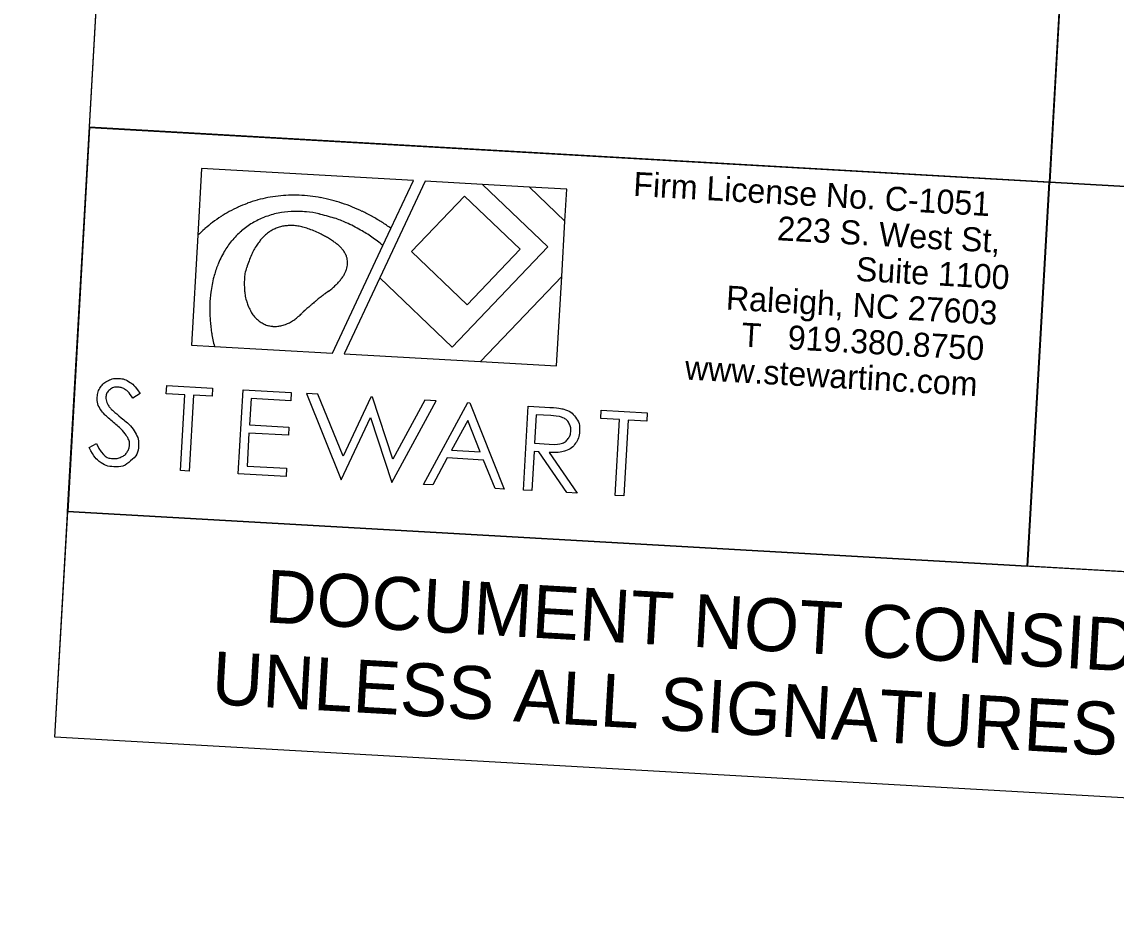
# Model space of a CAD drawing. Extents: x 2604316 to 2606605, y 617090 to 619543.
# Drawn here: x 2605834.5 to 2605948.3, y 618780.5 to 618872.2 of the extents above; entities that cross this region are included whole.
import ezdxf

# ---------------------------------------------------------------- set-up
doc = ezdxf.new("R2010")
doc.units = 0
for name, color, linetype in [('Default', 7, 'Continuous'), ('Scratch_Level_1', 7, 'Continuous'), ('Sheet Plan And Profile CELL', 7, 'Continuous')]:
    doc.layers.add(name, color=color, linetype=linetype)

msp = doc.modelspace()

# ---------------------------------------------------------------- linework, layer by layer
at = {"layer": 'Default'}
for p, q in [((2605947.83, 618967.86), (2605941.44, 618855.58)), ((2605853.21, 618856.96), (2605852.82, 618850.02)), ((2605875.25, 618855.7), (2605853.21, 618856.96)), ((2605876.48, 618855.63), (2605871.75, 618845.57)), ((2605872.91, 618850.72), (2605875.25, 618855.7)), ((2605882.42, 618855.29), (2605876.48, 618855.63)), ((2605882.42, 618855.29), (2605889.22, 618848.8)), ((2605887.31, 618855.02), (2605882.42, 618855.29)), ((2605889.22, 618848.8), (2605882.42, 618855.29)), ((2605891.19, 618854.79), (2605887.31, 618855.02)), ((2605887.31, 618855.02), (2605891, 618851.49)), ((2605891, 618851.49), (2605887.31, 618855.02)), ((2605891, 618851.49), (2605891.19, 618854.79)), ((2605859.05, 618853.68), (2605859, 618853.67)), ((2605865.58, 618853.92), (2605865.59, 618853.92)), ((2605857.96, 618853.34), (2605857.94, 618853.31)), ((2605865.4, 618852.22), (2605865.44, 618852.24)), ((2605870.96, 618851.95), (2605870.97, 618851.95)), ((2605890.67, 618845.73), (2605891, 618851.49)), ((2605872.08, 618848.95), (2605872.91, 618850.72)), ((2605852.82, 618850.02), (2605852.17, 618838.58)), ((2605866.82, 618837.75), (2605872.08, 618848.95)), ((2605889.22, 618848.8), (2605879.27, 618838.39)), ((2605879.27, 618838.39), (2605889.22, 618848.8)), ((2605880.84, 618842.77), (2605886.36, 618848.55)), ((2605890.67, 618845.73), (2605882.21, 618836.87)), ((2605882.21, 618836.87), (2605890.67, 618845.73)), ((2605890.14, 618836.42), (2605890.67, 618845.73)), ((2605871.75, 618845.57), (2605868.05, 618837.68)), ((2605879.27, 618838.39), (2605871.75, 618845.57)), ((2605871.75, 618845.57), (2605879.27, 618838.39)), ((2605852.17, 618838.58), (2605854.54, 618838.45)), ((2605854.54, 618838.45), (2605866.82, 618837.75)), ((2605868.05, 618837.68), (2605882.21, 618836.87)), ((2605882.21, 618836.87), (2605890.14, 618836.42)), ((2605865.31, 618833.5), (2605864.12, 618833.57)), ((2605864.12, 618833.57), (2605867.74, 618824.6)), ((2605867.93, 618827.03), (2605865.31, 618833.5)), ((2605870.81, 618833.19), (2605867.93, 618827.03)), ((2605870.98, 618833.18), (2605870.81, 618833.19)), ((2605873.09, 618826.74), (2605870.98, 618833.18)), ((2605872.99, 618824.3), (2605877.61, 618832.8)), ((2605876.42, 618832.87), (2605873.09, 618826.74)), ((2605877.61, 618832.8), (2605876.42, 618832.87)), ((2605867.74, 618824.6), (2605870.77, 618831.06)), ((2605870.77, 618831.06), (2605872.99, 618824.3)), ((2605837.94, 618797.83), (2605839.28, 618821.29)), ((2605837.94, 618797.83), (2605839.28, 618821.29)), ((2605839.28, 618821.29), (2606038.99, 618809.92)), ((2605839.28, 618821.29), (2606038.99, 618809.92)), ((2606037.66, 618786.46), (2605837.94, 618797.83)), ((2606037.66, 618786.46), (2605837.94, 618797.83))]:
    msp.add_line(p, q, dxfattribs=at)
for points in [[(2605841.54, 618861.23), (2605941.38, 618855.54), (2605939.1, 618815.61), (2605839.27, 618821.29)], [(2605941.38, 618855.54), (2605841.54, 618861.23), (2605839.27, 618821.29), (2605939.1, 618815.61)], [(2605941.43, 618855.54), (2606041.27, 618849.85), (2606038.99, 618809.92), (2605939.15, 618815.61)]]:
    msp.add_lwpolyline(points, close=True, dxfattribs=at)
for points in [[(2605875.04, 618848.31), (2605880.56, 618854.09), (2605886.36, 618848.55), (2605880.84, 618842.77), (2605875.04, 618848.31)], [(2605886.36, 618848.55), (2605880.56, 618854.09), (2605875.04, 618848.31), (2605880.84, 618842.77)], [(2605856.98, 618852.92), (2605857.06, 618852.96)], [(2605867.05, 618851.79), (2605867.01, 618851.78)], [(2605853.57, 618850.7), (2605853.5, 618850.66)], [(2605866.17, 618844.02), (2605866.05, 618843.93)], [(2605866.36, 618844.15), (2605866.28, 618844.1)], [(2605866.5, 618844.23), (2605866.42, 618844.19)], [(2605863.86, 618842.11), (2605863.75, 618842.01)], [(2605849.53, 618833.54), (2605849.58, 618834.39), (2605854.36, 618834.12), (2605854.32, 618833.27), (2605852.37, 618833.38), (2605851.92, 618825.5), (2605851.03, 618825.55), (2605851.48, 618833.43), (2605849.53, 618833.54)], [(2605846.81, 618833.55), (2605846.06, 618833.06)], [(2605857.53, 618833.94), (2605862.53, 618833.66), (2605862.49, 618832.8), (2605858.35, 618833.04), (2605858.19, 618830.3), (2605862.29, 618830.07), (2605862.25, 618829.21), (2605858.14, 618829.44), (2605857.95, 618826.01), (2605862.05, 618825.78), (2605862, 618824.92), (2605857.03, 618825.21), (2605857.53, 618833.94)], [(2605881.11, 618832.6), (2605884.69, 618823.63), (2605883.74, 618823.68), (2605882.53, 618826.64), (2605878.77, 618826.86), (2605877.25, 618824.05), (2605876.28, 618824.11), (2605880.9, 618832.61), (2605881.11, 618832.6)], [(2605889.37, 618827.43), (2605892.28, 618823.2), (2605891.2, 618823.26), (2605888.29, 618827.49), (2605887.8, 618827.52), (2605887.57, 618823.47), (2605886.7, 618823.52), (2605887.19, 618832.25)], [(2605887.19, 618832.25), (2605888.93, 618832.15)], [(2605888.02, 618831.35), (2605887.85, 618828.38), (2605889.35, 618828.28)], [(2605889.55, 618831.26), (2605888.02, 618831.35)], [(2605894.73, 618830.96), (2605894.78, 618831.82), (2605899.56, 618831.55), (2605899.51, 618830.69), (2605897.57, 618830.8), (2605897.12, 618822.92), (2605896.23, 618822.97), (2605896.67, 618830.85), (2605894.73, 618830.96)], [(2605880.89, 618830.76), (2605879.22, 618827.68), (2605882.2, 618827.51), (2605880.89, 618830.76)], [(2605841.51, 618827.94), (2605842.28, 618828.35)]]:
    msp.add_lwpolyline(points, dxfattribs=at)
for centre, radius, start, end in [((2605862.76, 618840.07), 14.11, 105.4351, 109.8733), ((2605862.76, 618840.07), 14.11, 105.4351, 109.8733), ((2605862.65, 618840.64), 13.53, 100.9183, 105.4351), ((2605862.65, 618840.64), 13.53, 100.9183, 105.4351), ((2605862.76, 618840.07), 14.11, 96.4841, 100.9183), ((2605862.76, 618840.07), 14.11, 96.4841, 100.9183), ((2605862.78, 618839.88), 14.3, 92.0792, 96.4841), ((2605862.78, 618839.88), 14.3, 92.0792, 96.4841), ((2605862.79, 618839.62), 14.57, 87.7544, 92.0792), ((2605862.79, 618839.62), 14.57, 87.7544, 92.0792), ((2605862.76, 618838.73), 15.45, 83.5548, 87.7544), ((2605862.76, 618838.73), 15.45, 83.5548, 87.7544), ((2605862.76, 618838.73), 15.45, 79.4225, 83.5548), ((2605862.76, 618838.73), 15.45, 79.4225, 83.5548), ((2605862.48, 618837.28), 16.93, 75.4903, 79.4225), ((2605862.48, 618837.28), 16.93, 75.4903, 79.4225), ((2605862.62, 618837.84), 16.35, 71.6037, 75.4903), ((2605862.62, 618837.84), 16.35, 71.6037, 75.4903), ((2605862.39, 618840.98), 13.11, 118.7212, 123.1234), ((2605862.39, 618840.98), 13.11, 118.7212, 123.1234), ((2605862.95, 618839.96), 14.27, 114.3893, 118.7212), ((2605862.95, 618839.96), 14.27, 114.3893, 118.7212), ((2605862.39, 618840.98), 13.11, 109.8733, 114.3893), ((2605862.39, 618840.98), 13.11, 109.8733, 114.3893), ((2605862.93, 618843.83), 8.65, 92.7105, 101.7301), ((2605862.93, 618843.83), 8.65, 92.7105, 101.7301), ((2605863.08, 618840.53), 11.96, 85.0393, 92.7105), ((2605863.08, 618840.53), 11.96, 85.0393, 92.7105), ((2605861.89, 618835.63), 18.68, 67.9682, 71.6037), ((2605861.89, 618835.63), 18.68, 67.9682, 71.6037), ((2605862.32, 618836.7), 17.52, 64.3511, 67.9682), ((2605862.32, 618836.7), 17.52, 64.3511, 67.9682), ((2605860.99, 618833.93), 20.6, 61.0149, 64.3511), ((2605860.99, 618833.93), 20.6, 61.0149, 64.3511), ((2605862.75, 618840.3), 13.88, 127.2527, 131.4472), ((2605862.75, 618840.3), 13.88, 127.2527, 131.4472), ((2605863.37, 618839.49), 14.9, 123.1234, 127.2527), ((2605863.37, 618839.49), 14.9, 123.1234, 127.2527), ((2605862.63, 618844.36), 8.06, 110.9978, 120.9124), ((2605862.63, 618844.36), 8.06, 110.9978, 120.9124), ((2605863.04, 618843.27), 9.23, 101.7301, 110.9978), ((2605863.04, 618843.27), 9.23, 101.7301, 110.9978), ((2605863.23, 618842.28), 10.21, 77.5039, 85.0393), ((2605863.23, 618842.28), 10.21, 77.5039, 85.0393), ((2605861.98, 618836.81), 15.79, 71.4506, 77.5039), ((2605861.98, 618836.81), 15.79, 71.4506, 77.5039), ((2605863.17, 618840.24), 12.19, 65.3226, 71.4506), ((2605863.17, 618840.24), 12.19, 65.3226, 71.4506), ((2605859.92, 618833.15), 19.99, 60.538, 65.3226), ((2605859.92, 618833.15), 19.99, 60.538, 65.3226), ((2605861.39, 618834.66), 19.77, 57.6686, 61.0149), ((2605861.39, 618834.66), 19.77, 57.6686, 61.0149), ((2605861.39, 618834.66), 19.77, 54.3325, 57.6686), ((2605861.39, 618834.66), 19.77, 54.3325, 57.6686), ((2605862.95, 618839.96), 14.27, 131.4472, 135.2253), ((2605862.95, 618839.96), 14.27, 131.4472, 135.2253), ((2605863.13, 618843.79), 8.82, 130.9224, 140.4448), ((2605863.13, 618843.79), 8.82, 130.9224, 140.4448), ((2605862.59, 618844.43), 7.98, 120.9124, 130.9224), ((2605862.59, 618844.43), 7.98, 120.9124, 130.9224), ((2605862.58, 618846.98), 4.1, 122.8405, 129.5899), ((2605862.58, 618846.98), 4.1, 122.8405, 129.5899), ((2605862.38, 618847.29), 3.73, 115.7662, 122.8405), ((2605862.38, 618847.29), 3.73, 115.7662, 122.8405), ((2605862.35, 618847.35), 3.66, 108.568, 115.7662), ((2605862.35, 618847.35), 3.66, 108.568, 115.7662), ((2605862.38, 618847.25), 3.77, 101.4688, 108.568), ((2605862.38, 618847.25), 3.77, 101.4688, 108.568), ((2605862.41, 618847.12), 3.9, 94.642, 101.4688), ((2605862.41, 618847.12), 3.9, 94.642, 101.4688), ((2605862.46, 618846.53), 4.49, 88.28, 94.642), ((2605862.46, 618846.53), 4.49, 88.28, 94.642), ((2605862.45, 618846.19), 4.84, 82.4228, 88.28), ((2605862.45, 618846.19), 4.84, 82.4228, 88.28), ((2605862.29, 618845.03), 6.01, 77.1673, 82.4228), ((2605862.29, 618845.03), 6.01, 77.1673, 82.4228), ((2605862.16, 618844.46), 6.59, 72.4373, 77.1673), ((2605862.16, 618844.46), 6.59, 72.4373, 77.1673), ((2605861.59, 618842.65), 8.48, 68.2695, 72.4373), ((2605861.59, 618842.65), 8.48, 68.2695, 72.4373), ((2605860.84, 618840.77), 10.52, 64.5402, 68.2694), ((2605860.84, 618840.77), 10.52, 64.5402, 68.2694), ((2605861.74, 618842.66), 8.42, 60.3723, 64.5402), ((2605861.74, 618842.66), 8.42, 60.3723, 64.5402), ((2605861.98, 618836.81), 15.79, 55.5186, 60.538), ((2605861.98, 618836.81), 15.79, 55.5186, 60.538), ((2605862.62, 618844.22), 8.16, 140.4448, 149.8427), ((2605862.62, 618844.22), 8.16, 140.4448, 149.8427), ((2605863.79, 618845.83), 5.77, 141.6353, 146.8316), ((2605863.79, 618845.83), 5.77, 141.6353, 146.8316), ((2605863.4, 618846.15), 5.27, 135.8946, 141.6353), ((2605863.4, 618846.15), 5.27, 135.8946, 141.6353), ((2605862.75, 618846.77), 4.37, 129.5899, 135.8946), ((2605862.75, 618846.77), 4.37, 129.5899, 135.8946), ((2605863.06, 618844.02), 6.6, 60.6425, 64.5301), ((2605863.06, 618844.02), 6.6, 60.6425, 64.5301), ((2605862.05, 618842.22), 8.66, 57.2494, 60.6425), ((2605862.05, 618842.22), 8.66, 57.2494, 60.6425), ((2605863.13, 618843.9), 6.66, 53.3617, 57.2494), ((2605863.13, 618843.9), 6.66, 53.3617, 57.2494), ((2605864.2, 618845.34), 4.87, 48.816, 53.3617), ((2605864.2, 618845.34), 4.87, 48.816, 53.3617), ((2605861.08, 618835.5), 17.37, 50.734, 55.5186), ((2605861.08, 618835.5), 17.37, 50.734, 55.5186), ((2605865.14, 618842.76), 11.07, 149.8427, 157.9091), ((2605865.14, 618842.76), 11.07, 149.8427, 157.9091), ((2605867.93, 618843.63), 10.47, 155.566, 159.1904), ((2605867.93, 618843.63), 10.47, 155.566, 159.1904), ((2605865.76, 618844.62), 8.09, 151.4424, 155.566), ((2605865.76, 618844.62), 8.09, 151.4424, 155.566), ((2605865.09, 618844.98), 7.33, 146.8316, 151.4424), ((2605865.09, 618844.98), 7.33, 146.8316, 151.4424), ((2605864.58, 618845.78), 4.29, 43.5847, 48.816), ((2605864.58, 618845.78), 4.29, 43.5847, 48.816), ((2605865.38, 618846.53), 3.19, 37.517, 43.5847), ((2605865.38, 618846.53), 3.19, 37.517, 43.5847), ((2605865.66, 618846.75), 2.84, 30.6364, 37.517), ((2605865.66, 618846.75), 2.84, 30.6364, 37.517), ((2605866.16, 618847.04), 2.26, 22.9285, 30.6364), ((2605866.16, 618847.04), 2.26, 22.9285, 30.6364), ((2605866.31, 618847.11), 2.1, 14.5996, 22.9285), ((2605866.31, 618847.11), 2.1, 14.5996, 22.9285), ((2605863.6, 618843.38), 9.4, 157.9091, 165.8682), ((2605863.6, 618843.38), 9.4, 157.9091, 165.8682), ((2605870.25, 618842.75), 12.95, 159.1904, 162.434), ((2605870.25, 618842.75), 12.95, 159.1904, 162.434), ((2605866.47, 618847.15), 1.93, 5.9113, 14.5996), ((2605866.47, 618847.15), 1.93, 5.9113, 14.5996), ((2605866.27, 618847.16), 2.13, 348.9846, 357.2472), ((2605866.27, 618847.16), 2.13, 348.9846, 357.2472), ((2605866.47, 618847.15), 1.93, 357.2472, 5.9113), ((2605866.47, 618847.15), 1.93, 357.2472, 5.9113), ((2605868.58, 618842.12), 14.55, 165.8682, 172.2658), ((2605868.58, 618842.12), 14.55, 165.8682, 172.2658), ((2605865.23, 618844.93), 7.59, 171.6986, 175.8527), ((2605865.23, 618844.93), 7.59, 171.6986, 175.8527), ((2605867.79, 618843.53), 10.38, 162.434, 166.0583), ((2605867.79, 618843.53), 10.38, 162.434, 166.0583), ((2605864.23, 618848.14), 4.41, 323.4941, 328.6309), ((2605864.23, 618848.14), 4.41, 323.4941, 328.6309), ((2605865.2, 618847.54), 3.27, 328.6309, 334.5948), ((2605865.2, 618847.54), 3.27, 328.6309, 334.5948), ((2605865.53, 618847.38), 2.9, 334.5948, 341.3707), ((2605865.53, 618847.38), 2.9, 334.5948, 341.3707), ((2605866.1, 618847.19), 2.3, 341.3707, 348.9846), ((2605866.1, 618847.19), 2.3, 341.3707, 348.9846), ((2605864.43, 618844.99), 6.78, 175.8527, 180.2474), ((2605864.43, 618844.99), 6.78, 175.8527, 180.2474), ((2605866.4, 618845), 8.75, 180.2474, 184.4016), ((2605866.4, 618845), 8.75, 180.2474, 184.4016), ((2605862.31, 618849.57), 6.78, 308.0645, 311.8816), ((2605862.31, 618849.57), 6.78, 308.0645, 311.8816), ((2605860.9, 618851.14), 8.89, 311.8816, 315.2147), ((2605860.9, 618851.14), 8.89, 311.8816, 315.2147), ((2605862.36, 618849.7), 6.85, 315.2147, 319.0318), ((2605862.36, 618849.7), 6.85, 315.2147, 319.0318), ((2605863.74, 618848.49), 5.01, 319.0318, 323.4941), ((2605863.74, 618848.49), 5.01, 319.0318, 323.4941), ((2605865.31, 618842.57), 11.25, 172.2658, 178.7275), ((2605865.31, 618842.57), 11.25, 172.2658, 178.7275), ((2605863.04, 618844.74), 5.39, 184.4016, 189.6957), ((2605863.04, 618844.74), 5.39, 184.4016, 189.6957), ((2605864.62, 618845.01), 6.99, 189.6957, 194.9243), ((2605864.62, 618845.01), 6.99, 189.6957, 194.9243), ((2605888.25, 618815.24), 36.29, 129.1346, 129.5378), ((2605888.25, 618815.24), 36.29, 129.1346, 129.5378), ((2605886.21, 618817.75), 33.05, 128.6918, 129.1346), ((2605886.21, 618817.75), 33.05, 128.6918, 129.1346), ((2605882.53, 618822.34), 27.17, 128.2035, 128.6918), ((2605882.53, 618822.34), 27.17, 128.2035, 128.6918), ((2605878.23, 618827.81), 20.21, 127.6053, 128.2035), ((2605878.23, 618827.81), 20.21, 127.6053, 128.2035), ((2605875.54, 618831.3), 15.81, 126.929, 127.6053), ((2605875.54, 618831.3), 15.81, 126.929, 127.6053), ((2605871.77, 618836.32), 9.52, 125.9896, 126.929), ((2605870.06, 618838.67), 6.61, 124.8621, 125.9896), ((2605870.06, 618838.67), 6.61, 124.8621, 125.9896), ((2605868.08, 618841.52), 3.14, 123.0144, 124.8621), ((2605867.26, 618842.78), 1.64, 120.4582, 123.0144), ((2605867.26, 618842.78), 1.64, 120.4582, 123.0144), ((2605866.55, 618843.98), 0.249, 114.801, 120.4583), ((2605866.96, 618843.1), 1.22, 112.2448, 114.8011), ((2605872.66, 618842.4), 18.6, 178.7275, 183.7519), ((2605872.66, 618842.4), 18.6, 178.7275, 183.7519), ((2605862.17, 618844.36), 4.45, 194.9243, 201.4764), ((2605862.17, 618844.36), 4.45, 194.9243, 201.4764), ((2605862.81, 618844.61), 5.14, 201.4764, 208.2505), ((2605862.81, 618844.61), 5.14, 201.4764, 208.2505), ((2605885.74, 618817.9), 32.63, 131.7357, 132.11), ((2605885.74, 618817.9), 32.63, 131.7357, 132.11), ((2605882.61, 618821.41), 27.93, 131.3312, 131.7357), ((2605882.61, 618821.41), 27.93, 131.3312, 131.7357), ((2605892.13, 618810.58), 42.35, 130.989, 131.3311), ((2605892.13, 618810.58), 42.35, 130.989, 131.3311), ((2605887.81, 618815.56), 35.75, 130.6166, 130.989), ((2605887.81, 618815.56), 35.75, 130.6166, 130.989), ((2605895.02, 618807.14), 46.84, 130.277, 130.6166), ((2605895.02, 618807.14), 46.84, 130.277, 130.6166), ((2605890.18, 618812.86), 39.35, 129.9065, 130.277), ((2605890.18, 618812.86), 39.35, 129.9065, 130.277), ((2605892.78, 618809.76), 43.39, 129.5378, 129.9065), ((2605892.78, 618809.76), 43.39, 129.5378, 129.9065), ((2605868.93, 618842.16), 14.86, 183.7519, 188.9947), ((2605868.93, 618842.16), 14.86, 183.7519, 188.9947), ((2605861.39, 618843.85), 3.53, 208.2505, 216.4264), ((2605861.39, 618843.85), 3.53, 208.2505, 216.4264), ((2605861.46, 618843.9), 3.62, 216.4264, 225.1491), ((2605861.46, 618843.9), 3.62, 216.4264, 225.1491), ((2605860.95, 618843.38), 2.88, 225.1491, 234.9243), ((2605860.95, 618843.38), 2.88, 225.1491, 234.9243), ((2605859.68, 618845.86), 5.62, 299.4606, 305.066), ((2605859.68, 618845.86), 5.62, 299.4606, 305.066), ((2605860.21, 618845.1), 4.68, 305.066, 310.7971), ((2605860.21, 618845.1), 4.68, 305.066, 310.7971), ((2605860.08, 618845.26), 4.9, 310.7971, 316.4024), ((2605860.08, 618845.26), 4.9, 310.7971, 316.4024), ((2605882.55, 618821.56), 27.78, 132.5821, 132.9564), ((2605882.55, 618821.56), 27.78, 132.5821, 132.9564), ((2605875.57, 618829.15), 17.46, 132.11, 132.5821), ((2605860.85, 618843.24), 2.71, 234.9243, 245.3087), ((2605860.85, 618843.24), 2.71, 234.9243, 245.3087), ((2605860.85, 618843.25), 2.73, 245.3087, 255.659), ((2605860.85, 618843.25), 2.73, 245.3087, 255.659), ((2605860.78, 618842.97), 2.43, 255.659, 266.2495), ((2605860.78, 618842.97), 2.43, 255.659, 266.2495), ((2605860.83, 618843.69), 3.16, 266.2495, 275.5332), ((2605860.83, 618843.69), 3.16, 266.2495, 275.5332), ((2605860.87, 618843.21), 2.67, 275.5332, 284.7506), ((2605860.87, 618843.21), 2.67, 275.5332, 284.7506), ((2605860.49, 618844.66), 4.18, 284.7505, 292.1193), ((2605860.49, 618844.66), 4.18, 284.7505, 292.1193), ((2605860.83, 618843.83), 3.28, 292.1193, 299.4606), ((2605860.83, 618843.83), 3.28, 292.1193, 299.4606), ((2605870.23, 618842.37), 16.17, 188.9947, 194.0191), ((2605870.23, 618842.37), 16.17, 188.9947, 194.0191)]:
    msp.add_arc(centre, radius, start, end, dxfattribs=at)
for points in [[(2605846.06, 618833.06), (2605845.61, 618833.74), (2605845.27, 618833.96), (2605844.94, 618834.19), (2605844.53, 618834.21), (2605844, 618834.24), (2605843.65, 618833.94), (2605843.29, 618833.64), (2605843.26, 618833.17), (2605843.25, 618832.89), (2605843.35, 618832.61), (2605843.46, 618832.34), (2605843.75, 618832.01), (2605843.91, 618831.83), (2605844.83, 618831.07), (2605845.92, 618830.17), (2605846.3, 618829.49), (2605846.69, 618828.81), (2605846.65, 618828.16), (2605846.59, 618827.21), (2605845.83, 618826.55), (2605845.07, 618825.89), (2605844.04, 618825.95), (2605843.25, 618825.99), (2605842.62, 618826.45), (2605842, 618826.91), (2605841.51, 618827.94)], [(2605842.28, 618828.35), (2605842.98, 618826.86), (2605844.01, 618826.8), (2605844.45, 618826.77), (2605844.84, 618826.96), (2605845.24, 618827.14), (2605845.46, 618827.47), (2605845.68, 618827.81), (2605845.71, 618828.19), (2605845.73, 618828.63), (2605845.46, 618829.07), (2605845.08, 618829.67), (2605844.04, 618830.56), (2605843, 618831.44), (2605842.75, 618831.83), (2605842.32, 618832.47), (2605842.36, 618833.19), (2605842.4, 618833.76), (2605842.7, 618834.21), (2605843, 618834.67), (2605843.51, 618834.91), (2605844.02, 618835.15), (2605844.6, 618835.12), (2605845.22, 618835.08), (2605845.73, 618834.75), (2605846.25, 618834.41), (2605846.81, 618833.55)], [(2605888.93, 618832.15), (2605890.38, 618832.07), (2605890.89, 618831.92), (2605891.66, 618831.7), (2605892.11, 618831.09), (2605892.56, 618830.47), (2605892.52, 618829.62), (2605892.47, 618828.9), (2605892.11, 618828.38), (2605891.74, 618827.86), (2605891.1, 618827.62), (2605890.47, 618827.37), (2605889.37, 618827.43)], [(2605889.35, 618828.28), (2605890.22, 618828.23), (2605890.65, 618828.37), (2605891.08, 618828.51), (2605891.34, 618828.87), (2605891.59, 618829.22), (2605891.62, 618829.67), (2605891.64, 618830.11), (2605891.42, 618830.48), (2605891.21, 618830.86), (2605890.83, 618831.03), (2605890.45, 618831.21), (2605889.55, 618831.26)]]:
    msp.add_open_spline(points, degree=3, dxfattribs=at)
at = {"layer": 'Scratch_Level_1'}
msp.add_lwpolyline([(2606037.66, 618786.46), (2605837.94, 618797.83), (2605849.36, 618998.56), (2604589.3, 619070.32), (2604537.44, 618159.71), (2605997.22, 618076.57)], close=True, dxfattribs=at)
msp.add_lwpolyline([(2606037.66, 618786.46), (2605837.94, 618797.83), (2605849.36, 618998.56), (2604589.3, 619070.32), (2604537.44, 618159.71), (2605997.22, 618076.57)], close=True, dxfattribs=at)
at = {"layer": 'Sheet Plan And Profile CELL'}
for p, q in [((2605841.54, 618861.23), (2605839.28, 618821.29)), ((2605941.43, 618855.54), (2605939.13, 618815.61)), ((2605839.28, 618821.29), (2606038.99, 618809.92))]:
    msp.add_line(p, q, dxfattribs=at)
for points in [[(2605847.94, 618973.55), (2605947.83, 618967.86), (2605941.43, 618855.53), (2605841.55, 618861.24)], [(2605947.83, 618967.86), (2606047.65, 618962.19), (2606041.27, 618849.85), (2605941.43, 618855.53)]]:
    msp.add_lwpolyline(points, close=True, dxfattribs=at)

# ---------------------------------------------------------------- texts
at = {"layer": 'Default'}
for s, height, p in [('Firm License No. C-1051', 2.5, (2605898.07, 618854.11)), ('223 S. West St,', 2.5, (2605913.04, 618849.5)), ('Suite 1100', 2.5, (2605921.22, 618845.28)), ('Raleigh, NC 27603', 2.5, (2605907.71, 618842.29)), ('T   919.380.8750', 2.5, (2605909.31, 618838.44)), ('www.stewartinc.com', 2.5, (2605903.44, 618835.02)), ('DOCUMENT NOT CONSIDERED FINAL', 5.5, (2605859.73, 618809.77)), ('DOCUMENT NOT CONSIDERED FINAL', 5.5, (2605859.73, 618809.77)), ('UNLESS ALL SIGNATURES COMPLETED', 5.5, (2605854.16, 618801.27)), ('UNLESS ALL SIGNATURES COMPLETED', 5.5, (2605854.16, 618801.27))]:
    msp.add_text(s, height=height, rotation=356.7403, dxfattribs=at).set_placement(p)

doc.saveas('drawing.dxf')
